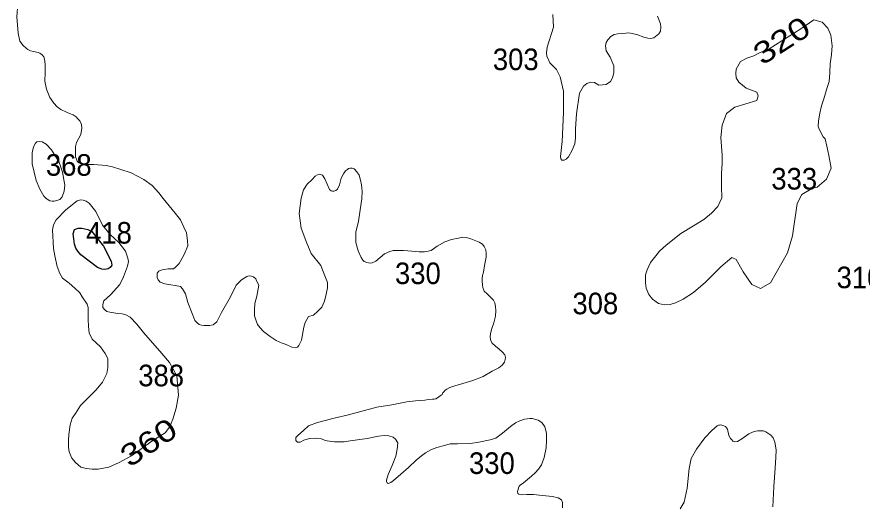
# Model space of a CAD drawing. Extents: x 445.4 to 500, y 8728.7 to 8784.
# Drawn here: x 465.36 to 471.62, y 8775.3 to 8778.91 of the extents above; entities that cross this region are included whole.
import ezdxf
from ezdxf.enums import TextEntityAlignment as Align

# ---------------------------------------------------------------- set-up
doc = ezdxf.new("R2010")
doc.units = 0
doc.header["$LTSCALE"] = 0.064
doc.layers.add('1', color=7, linetype='Continuous', lineweight=25)
doc.layers.add('2', color=7, linetype='Continuous', lineweight=13)
doc.layers.add('21', color=7, linetype='Continuous')
doc.layers.add('61', color=7, linetype='Continuous')

msp = doc.modelspace()

# ---------------------------------------------------------------- linework, layer by layer
at = {"layer": '1'}
msp.add_lwpolyline([(465.7848, 8777.3322), (465.8123, 8777.3414), (465.8399, 8777.3429), (465.8858, 8777.3322), (465.9133, 8777.3184), (466.0005, 8777.2084), (466.0571, 8777.0969), (466.0617, 8777.0679), (466.051, 8777.0511), (466.0357, 8777.0404), (466.0112, 8777.0358), (465.9883, 8777.0388), (465.9561, 8777.0511), (465.8337, 8777.1443), (465.8108, 8777.1718), (465.797, 8777.1932), (465.7848, 8777.2237), (465.7802, 8777.2634), (465.7771, 8777.3001)], close=True, dxfattribs=at)
at = {"layer": '2'}
for points in [[(466.3983, 8777.0092), (466.4103, 8777.0237), (466.4272, 8777.0309), (466.4465, 8777.0357), (466.4657, 8777.0381), (466.4802, 8777.0405), (466.5043, 8777.0405), (466.5188, 8777.0405), (466.5332, 8777.0525), (466.5621, 8777.0814), (466.5983, 8777.1463), (466.6254, 8777.2101), (466.623, 8777.251), (466.6158, 8777.3063), (466.5965, 8777.3496), (466.57, 8777.4026), (466.5315, 8777.4531), (466.4422, 8777.5622), (466.4119, 8777.6031), (466.3621, 8777.6581), (466.2998, 8777.7026), (466.2055, 8777.7523), (466.1289, 8777.7772), (466.0684, 8777.7967), (466.0203, 8777.8056), (465.9296, 8777.8127), (465.8833, 8777.8127), (465.8352, 8777.8198), (465.8174, 8777.8252), (465.8049, 8777.8376), (465.7996, 8777.8518), (465.7943, 8777.8696), (465.7925, 8777.9104), (465.7925, 8777.9477), (465.7995, 8777.9767), (465.8335, 8778.0349), (465.8408, 8778.0833), (465.8384, 8778.11), (465.8262, 8778.1367), (465.8092, 8778.1536), (465.7971, 8778.1657), (465.7753, 8778.1803), (465.7485, 8778.1924), (465.7267, 8778.2021), (465.6854, 8778.2215), (465.6587, 8778.2409), (465.632, 8778.2675), (465.6029, 8778.3087), (465.5786, 8778.3717), (465.5664, 8778.4299), (465.568, 8778.4945), (465.568, 8778.5575), (465.5631, 8778.5938), (465.5582, 8778.6108), (465.5461, 8778.6253), (465.5291, 8778.6375), (465.517, 8778.6423), (465.483, 8778.6496), (465.4611, 8778.6544), (465.4393, 8778.6641), (465.4271, 8778.6762), (465.4053, 8778.6956), (465.381, 8778.7271), (465.3689, 8778.7853), (465.3592, 8778.9065), (465.3668, 8779.0049)], [(470.1057, 8778.9131), (470.1281, 8778.8566), (470.131, 8778.8298), (470.1281, 8778.8001), (470.1147, 8778.7822), (470.0774, 8778.7525), (470.0521, 8778.7466), (470.0328, 8778.7495), (470.0045, 8778.757), (469.9509, 8778.7763), (469.892, 8778.7881), (469.8488, 8778.7836), (469.8116, 8778.7822), (469.7848, 8778.7762), (469.7595, 8778.7613), (469.7372, 8778.7376), (469.7253, 8778.7182), (469.7208, 8778.6915), (469.7253, 8778.6558), (469.7536, 8778.6097), (469.7819, 8778.5443), (469.7819, 8778.4922), (469.7714, 8778.4555), (469.7566, 8778.4287), (469.7238, 8778.4049), (469.6702, 8778.4019), (469.639, 8778.4213), (469.6122, 8778.4242), (469.5824, 8778.4123), (469.5571, 8778.3945), (469.5273, 8778.341), (469.505, 8778.1893), (469.4989, 8778.0785), (469.4989, 8778.0101), (469.4929, 8777.967), (469.4736, 8777.9194), (469.4468, 8777.8704), (469.4275, 8777.8525), (469.4141, 8777.8466), (469.4051, 8777.8451), (469.3962, 8777.8451), (469.3902, 8777.8555), (469.3858, 8777.8733), (469.3977, 8777.9849), (469.4081, 8778.1975), (469.4096, 8778.356), (469.3842, 8778.4616), (469.356, 8778.5166), (469.3083, 8778.5672), (469.2857, 8778.6171), (469.2828, 8778.6409), (469.2872, 8778.6826), (469.3348, 8778.8298), (469.3289, 8778.9249)], [(467.914, 8777.5592), (467.9183, 8777.6141), (467.9129, 8777.6635), (467.9053, 8777.6969), (467.8946, 8777.7335), (467.8784, 8777.7582), (467.859, 8777.7808), (467.8439, 8777.7862), (467.8288, 8777.7862), (467.817, 8777.783), (467.8073, 8777.7776), (467.7932, 8777.7668), (467.7782, 8777.7453), (467.7609, 8777.712), (467.748, 8777.6635), (467.734, 8777.6313), (467.7232, 8777.6216), (467.7103, 8777.6162), (467.6984, 8777.6162), (467.6865, 8777.6194), (467.6747, 8777.6291), (467.6574, 8777.6689), (467.6402, 8777.7077), (467.6229, 8777.7335), (467.6089, 8777.7399), (467.5982, 8777.741), (467.5852, 8777.7378), (467.5701, 8777.727), (467.5464, 8777.7023), (467.5086, 8777.6667), (467.4821, 8777.6258), (467.4653, 8777.5633), (467.4508, 8777.4503), (467.4653, 8777.3409), (467.5062, 8777.2303), (467.54, 8777.1533), (467.6099, 8777.0643), (467.6409, 8776.9884), (467.6602, 8776.9403), (467.6602, 8776.8994), (467.6506, 8776.8537), (467.6385, 8776.8008), (467.6193, 8776.7575), (467.5879, 8776.7262), (467.5566, 8776.6974), (467.5205, 8776.6878), (467.506, 8776.6661), (467.4939, 8776.6421), (467.4843, 8776.6084), (467.4674, 8776.5122), (467.4482, 8776.4737), (467.4385, 8776.4593), (467.4241, 8776.4545), (467.3951, 8776.4617), (467.3532, 8776.479), (467.3243, 8776.491), (467.2809, 8776.5103), (467.2352, 8776.5391), (467.187, 8776.5776), (467.1605, 8776.6041), (467.1412, 8776.6281), (467.1315, 8776.6546), (467.1195, 8776.693), (467.1195, 8776.7363), (467.1219, 8776.7844), (467.1364, 8776.8374), (467.1508, 8776.9191), (467.1339, 8776.9528), (467.1291, 8776.9672), (467.1123, 8776.9817), (467.0978, 8776.9865), (467.0857, 8776.9889), (467.0689, 8776.9865), (467.0617, 8776.9841), (467.0231, 8776.96), (466.9845, 8776.9191), (466.9412, 8776.8325), (466.8761, 8776.7171), (466.84, 8776.6474), (466.8134, 8776.6257), (466.7869, 8776.6209), (466.7677, 8776.6209), (466.746, 8776.6209), (466.7267, 8776.6233), (466.7098, 8776.6281), (466.6954, 8776.6401), (466.6785, 8776.657), (466.6616, 8776.6979), (466.6248, 8776.7904), (466.6079, 8776.8553), (466.5862, 8776.8914), (466.5718, 8776.9106), (466.5597, 8776.913), (466.5453, 8776.9154), (466.5308, 8776.9178), (466.4995, 8776.9226), (466.4561, 8776.9299), (466.42, 8776.9419), (466.4055, 8776.9587), (466.3983, 8776.9756), (466.3983, 8777.0092)], [(467.4574, 8775.7567), (467.4383, 8775.7567), (467.4249, 8775.77), (467.4249, 8775.7814), (467.4268, 8775.791), (467.4402, 8775.8062), (467.4822, 8775.8443), (467.5184, 8775.8766), (467.5871, 8775.9014), (467.7092, 8775.9337), (467.816, 8775.9585), (468.0249, 8776.0157), (468.1367, 8776.0329), (468.2472, 8776.0555), (468.3111, 8776.0622), (468.3811, 8776.0679), (468.409, 8776.0719), (468.437, 8776.0745), (468.4503, 8776.0745), (468.4636, 8776.0772), (468.4756, 8776.0852), (468.4942, 8776.1011), (468.5089, 8776.1091), (468.5156, 8776.121), (468.5249, 8776.133), (468.5315, 8776.1423), (468.5435, 8776.1489), (468.5661, 8776.1609), (468.6048, 8776.1742), (468.662, 8776.1915), (468.7379, 8776.2127), (468.8141, 8776.244), (468.8807, 8776.2839), (468.9286, 8776.3078), (468.9539, 8776.3277), (468.9712, 8776.349), (468.9778, 8776.3689), (468.9792, 8776.3848), (468.9752, 8776.4048), (468.9565, 8776.4234), (468.9326, 8776.446), (468.9059, 8776.4679), (468.8793, 8776.4905), (468.87, 8776.5078), (468.866, 8776.5344), (468.8687, 8776.561), (468.8766, 8776.5982), (468.8926, 8776.6407), (468.9046, 8776.6898), (468.9086, 8776.7324), (468.9059, 8776.7629), (468.9006, 8776.7882), (468.8891, 8776.8098), (468.8701, 8776.8276), (468.8433, 8776.8555), (468.8221, 8776.8744), (468.8121, 8776.9023), (468.8076, 8776.9223), (468.8054, 8776.9491), (468.8054, 8776.9702), (468.8076, 8776.9903), (468.8154, 8777.0148), (468.8243, 8777.0646), (468.8355, 8777.1259), (468.8355, 8777.1571), (468.8333, 8777.1816), (468.8199, 8777.2072), (468.8087, 8777.2228), (468.7852, 8777.2373), (468.7473, 8777.2529), (468.7216, 8777.2629), (468.6892, 8777.2718), (468.6636, 8777.2741), (468.6297, 8777.2671), (468.579, 8777.2574), (468.5284, 8777.2406), (468.473, 8777.2093), (468.4272, 8777.1757), (468.3935, 8777.1684), (468.379, 8777.166), (468.3405, 8777.166), (468.314, 8777.1684), (468.2561, 8777.1733), (468.2224, 8777.1757), (468.1911, 8777.1757), (468.1477, 8777.1757), (468.1212, 8777.1684), (468.0826, 8777.1516), (468.0176, 8777.0963), (467.9911, 8777.0843), (467.9766, 8777.0819), (467.9525, 8777.0867), (467.9332, 8777.0939), (467.9212, 8777.1059), (467.9091, 8777.1252), (467.8874, 8777.1733), (467.8706, 8777.2358), (467.8706, 8777.3128), (467.8899, 8777.3945), (467.9107, 8777.528), (467.914, 8777.5592)], [(469.4005, 8775.2702), (469.4016, 8775.3099), (469.3949, 8775.3289), (469.3694, 8775.3452), (469.3277, 8775.3542), (469.2533, 8775.3615), (469.1861, 8775.3687), (469.1371, 8775.3687), (469.0953, 8775.3669), (469.0772, 8775.3724), (469.0699, 8775.3778), (469.0681, 8775.3923), (469.0717, 8775.4068), (469.0754, 8775.4177), (469.0808, 8775.4303), (469.0881, 8775.4394), (469.1135, 8775.4557), (469.1425, 8775.4811), (469.1716, 8775.5046), (469.1988, 8775.53), (469.2242, 8775.5572), (469.246, 8775.5898), (469.2657, 8775.6433), (469.2802, 8775.7139), (469.2838, 8775.7683), (469.282, 8775.8245), (469.2711, 8775.8716), (469.2493, 8775.9024), (469.2203, 8775.9205), (469.1767, 8775.9314), (469.1604, 8775.9314), (469.1205, 8775.9277), (469.086, 8775.9151), (469.0533, 8775.8988), (469.0152, 8775.8734), (468.9571, 8775.8227), (468.9081, 8775.7864), (468.8663, 8775.7737), (468.781, 8775.7556), (468.7193, 8775.7466), (468.6226, 8775.7436), (468.5699, 8775.7436), (468.5263, 8775.7328), (468.4701, 8775.7183), (468.4301, 8775.702), (468.3866, 8775.6766), (468.3575, 8775.6567), (468.3176, 8775.6223), (468.2595, 8775.5697), (468.2032, 8775.519), (468.1488, 8775.4719), (468.1306, 8775.4574), (468.1088, 8775.4501), (468.1016, 8775.4556), (468.0979, 8775.4646), (468.0979, 8775.4755), (468.1106, 8775.5172), (468.1403, 8775.5834), (468.167, 8775.652), (468.1765, 8775.7053), (468.1803, 8775.7529), (468.1632, 8775.7795), (468.146, 8775.7948), (468.1136, 8775.8043), (468.0792, 8775.8062), (468.0392, 8775.8024), (467.9533, 8775.7852), (467.8293, 8775.7662), (467.7836, 8775.7605), (467.713, 8775.7586), (467.6901, 8775.7624), (467.6424, 8775.77), (467.6157, 8775.7814), (467.5794, 8775.7871), (467.526, 8775.7833), (467.486, 8775.7719), (467.4574, 8775.7567)], [(470.9597, 8775.2771), (470.966, 8775.4262), (470.9766, 8775.5658), (470.9829, 8775.6441), (470.985, 8775.7012), (470.9744, 8775.7561), (470.9617, 8775.7879), (470.9448, 8775.809), (470.93, 8775.8175), (470.9088, 8775.8323), (470.8897, 8775.8407), (470.8494, 8775.8407), (470.8346, 8775.8386), (470.8092, 8775.8302), (470.7816, 8775.8175), (470.7308, 8775.7815), (470.699, 8775.7625), (470.6778, 8775.7604), (470.663, 8775.7646), (470.6566, 8775.7731), (470.646, 8775.7836), (470.6333, 8775.8069), (470.6227, 8775.8534), (470.6079, 8775.8725), (470.5888, 8775.8809), (470.574, 8775.8851), (470.5634, 8775.883), (470.557, 8775.883), (470.5465, 8775.8788), (470.5083, 8775.8428), (470.4553, 8775.79), (470.3939, 8775.7054), (470.3536, 8775.6356), (470.3407, 8775.5625), (470.3259, 8775.4166), (470.3026, 8775.313), (470.2729, 8775.2623)]]:
    msp.add_lwpolyline(points, dxfattribs=at)
for points in [[(470.6558, 8777.1243), (470.6874, 8777.111), (470.7396, 8777.0181), (470.8035, 8776.9251), (470.8673, 8776.8961), (470.9428, 8776.9368), (471.0676, 8777.1604), (471.1054, 8777.2852), (471.1402, 8777.5234), (471.175, 8777.5902), (471.2524, 8777.6374), (471.2875, 8777.6462), (471.3577, 8777.7041), (471.3928, 8777.7866), (471.3735, 8777.8797), (471.3594, 8777.95), (471.3463, 8778.0025), (471.3331, 8778.0184), (471.305, 8778.0694), (471.2962, 8778.094), (471.298, 8778.1379), (471.3068, 8778.1941), (471.3201, 8778.2488), (471.3384, 8778.2994), (471.3507, 8778.3416), (471.3629, 8778.3837), (471.3767, 8778.4274), (471.3811, 8778.4927), (471.3854, 8778.5581), (471.3941, 8778.6278), (471.3985, 8778.6931), (471.3898, 8778.7715), (471.368, 8778.8238), (471.3245, 8778.8674), (471.2635, 8778.8848), (471.1677, 8778.8195), (470.9326, 8778.6713), (470.8604, 8778.64), (470.8194, 8778.6191), (470.7672, 8778.6016), (470.7193, 8778.5755), (470.6891, 8778.5185), (470.6844, 8778.4884), (470.6886, 8778.4551), (470.7087, 8778.4222), (470.7628, 8778.3795), (470.8412, 8778.349), (470.8498, 8778.3226), (470.8414, 8778.2878), (470.6772, 8778.2382), (470.6163, 8778.1903), (470.5846, 8778.1047), (470.5756, 8778.0135), (470.5843, 8777.8829), (470.5843, 8777.8219), (470.58, 8777.7466), (470.58, 8777.6507), (470.5829, 8777.5665), (470.551, 8777.5026), (470.5045, 8777.4533), (470.4494, 8777.4068), (470.371, 8777.3603), (470.2781, 8777.3022), (470.1704, 8777.216), (470.1192, 8777.1722), (470.0827, 8777.1246), (470.0535, 8777.0881), (470.0274, 8777.0338), (470.0158, 8776.996), (470.0152, 8776.9364), (470.021, 8776.898), (470.041, 8776.8515), (470.0685, 8776.8171), (470.1127, 8776.785), (470.1574, 8776.773), (470.1993, 8776.7773), (470.2377, 8776.789), (470.2944, 8776.8154), (470.3707, 8776.8664), (470.4601, 8776.9412), (470.5745, 8777.0559)], [(465.6721, 8777.8297), (465.6165, 8777.9223), (465.5771, 8777.964), (465.5469, 8777.9813), (465.5272, 8777.9837), (465.5075, 8777.9825), (465.4971, 8777.9709), (465.4832, 8777.9455), (465.4727, 8777.8991), (465.4727, 8777.8181), (465.5029, 8777.6954), (465.5295, 8777.6317), (465.5597, 8777.5796), (465.5761, 8777.5605), (465.6039, 8777.5455), (465.6213, 8777.542), (465.6364, 8777.542), (465.6549, 8777.5466), (465.6781, 8777.5547), (465.6955, 8777.5744), (465.7083, 8777.6161), (465.7152, 8777.6601), (465.6978, 8777.7566)], [(466.4578, 8775.8251), (466.4907, 8775.8685), (466.5151, 8775.9279), (466.5396, 8776.0095), (466.5556, 8776.1047), (466.5439, 8776.2478), (466.4887, 8776.3464), (466.4333, 8776.414), (466.2964, 8776.5698), (466.2474, 8776.6309), (466.1985, 8776.6818), (466.1656, 8776.7009), (466.1402, 8776.7062), (466.1062, 8776.7104), (466.0478, 8776.72), (466.0255, 8776.7242), (466.0107, 8776.7359), (465.9969, 8776.7549), (465.9948, 8776.7761), (466.0043, 8776.8026), (466.0521, 8776.8493), (466.1211, 8776.9256), (466.1489, 8776.9804), (466.1786, 8777.0599), (466.1849, 8777.096), (466.1818, 8777.1193), (466.1648, 8777.1723), (466.1149, 8777.2348), (466.0508, 8777.296), (465.9924, 8777.3638), (465.9447, 8777.4645), (465.8934, 8777.5275), (465.8722, 8777.5413), (465.8509, 8777.5498), (465.8329, 8777.5508), (465.8053, 8777.5434), (465.7225, 8777.4766), (465.6503, 8777.4035), (465.631, 8777.3657), (465.6236, 8777.3307), (465.631, 8777.1918), (465.6395, 8777.1378), (465.6565, 8777.0572), (465.6767, 8777.0055), (465.6968, 8776.9726), (465.7467, 8776.9334), (465.7892, 8776.8974), (465.8253, 8776.8634), (465.8433, 8776.8327), (465.8794, 8776.7797), (465.8879, 8776.7543), (465.8861, 8776.6676), (465.8892, 8776.6135), (465.8956, 8776.5669), (465.9158, 8776.5202), (465.9795, 8776.464), (466.0126, 8776.4135), (466.0317, 8776.3764), (466.0338, 8776.351), (466.0338, 8776.3096), (466.0264, 8776.2662), (465.9935, 8776.2005), (465.9456, 8776.1447), (465.8299, 8776.0281), (465.7938, 8775.9698), (465.7683, 8775.9348), (465.7543, 8775.8852), (465.7437, 8775.8131), (465.7416, 8775.7728), (465.7426, 8775.7198), (465.7458, 8775.6859), (465.767, 8775.6393), (465.7925, 8775.6064), (465.8339, 8775.5725), (465.8732, 8775.5608), (465.9156, 8775.5566), (465.9623, 8775.5566), (466.0409, 8775.5714), (466.118, 8775.6071), (466.2093, 8775.6558), (466.36, 8775.764)]]:
    msp.add_lwpolyline(points, close=True, dxfattribs=at)

# ---------------------------------------------------------------- texts
at = {"layer": '21', "width": 0.95}
for s, p in [('303', (468.8853, 8778.5122)), ('368', (465.574, 8777.7301)), ('333', (470.9486, 8777.6279)), ('418', (465.8717, 8777.2275)), ('330', (468.1604, 8776.9275)), ('310', (471.4321, 8776.8972)), ('308', (469.4751, 8776.7042)), ('388', (466.2584, 8776.1706)), ('330', (468.7086, 8775.5214))]:
    msp.add_text(s, height=0.16, dxfattribs=at).set_placement(p)
at = {"layer": '61', "width": 1.25}
for s, rotation, p in [('320', 32.916, (471.0686, 8778.6649)), ('360', 33.695, (466.3792, 8775.6891))]:
    msp.add_text(s, height=0.16, rotation=rotation, dxfattribs=at).set_placement(p, align=Align.CENTER)

doc.saveas('drawing.dxf')
